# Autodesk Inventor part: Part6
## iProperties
Shininess: 64.0
Length Units: 11269
Angle Units: 11279
Time Units: 11290
Mass Units: 11283
Length Display Precision: 3
Angle Display Precision: 2
Compacted: True
Part Number: Part6
Document SubType Name: Modeling
Created: 2002-12
Designer: deepak
Density: 0.0
Volumn: 0.0
Area: 0.0
PropertySet Name: Model Information
Control State: 0
Master: False
Checked Out: False
Author: deepak
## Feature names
1. Extrusion1
